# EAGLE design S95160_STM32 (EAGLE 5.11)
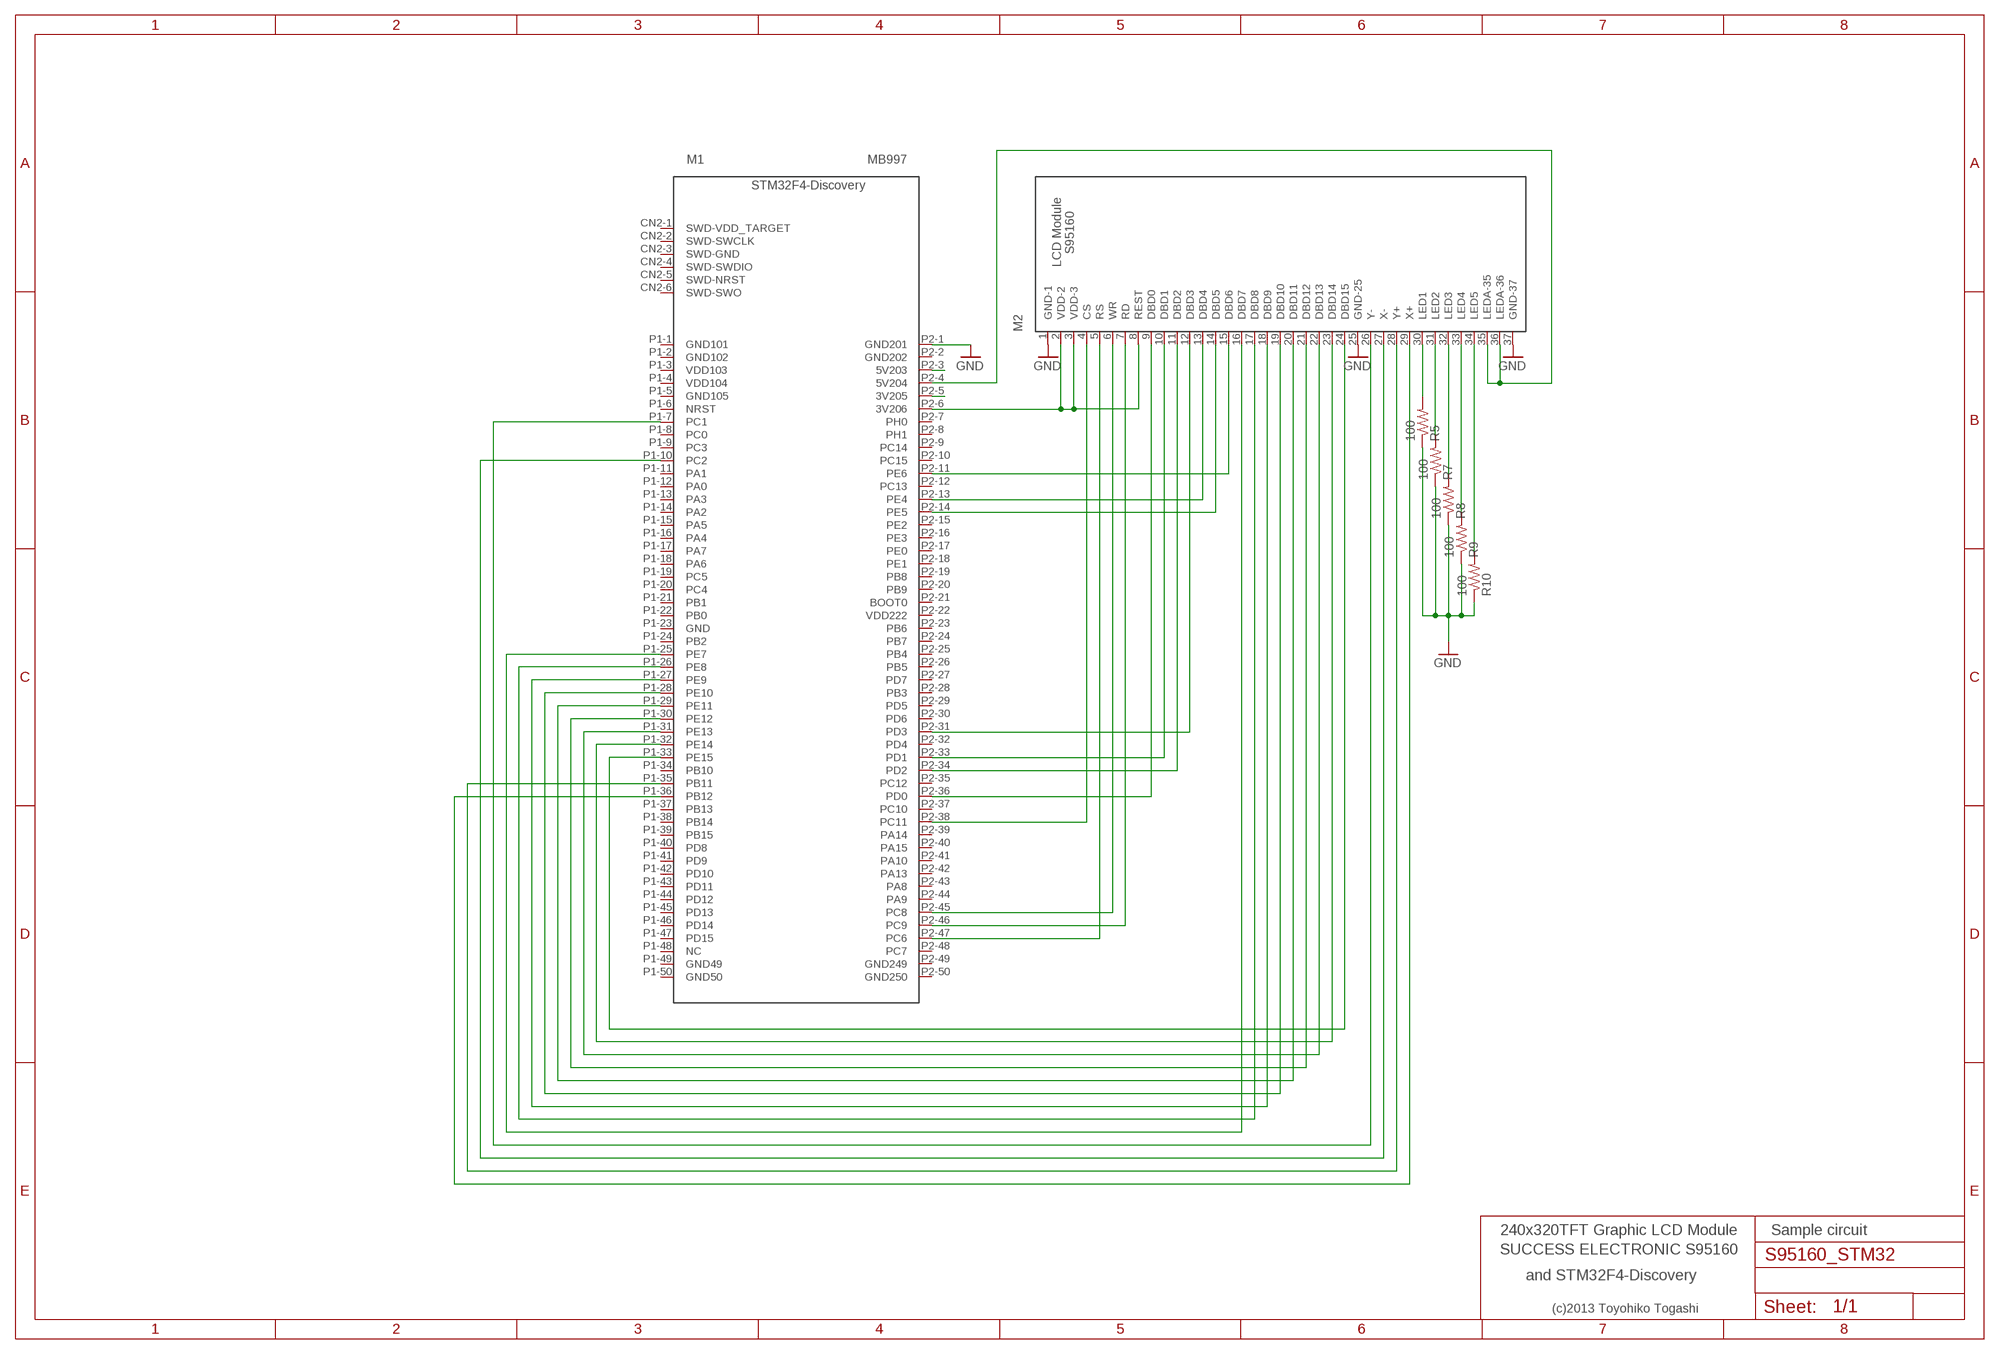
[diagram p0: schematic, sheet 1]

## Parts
M1  MB997  [MB997]
M2  S95160  [S95160]
R5  100  R-US_0204/5  [0204/5]
R7  100  R-US_0204/5  [0204/5]
R8  100  R-US_0204/5  [0204/5]
R9  100  R-US_0204/5  [0204/5]
R10  100  R-US_0204/5  [0204/5]

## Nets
GND: M1.P2-1(GND201) M2.1(GND-1) M2.25(GND-25) M2.37(GND-37) R5.1 R7.1 R8.1 R9.1 R10.1
N$1: M1.P2-36(PD0) M2.9(DBD0)
N$2: M1.P2-33(PD1) M2.10(DBD1)
N$3: M1.P2-6(3V206) M2.2(VDD-2) M2.3(VDD-3) M2.8(REST)
N$5: M1.P2-3(5V203)
N$6: M1.P2-5(3V205)
N$11: M1.P2-34(PD2) M2.11(DBD2)
N$14: M1.P2-4(5V204) M2.35(LEDA-35) M2.36(LEDA-36)
N$15: M1.P2-31(PD3) M2.12(DBD3)
N$17: M1.P2-13(PE4) M2.13(DBD4)
N$18: M1.P2-14(PE5) M2.14(DBD5)
N$19: M1.P2-11(PE6) M2.15(DBD6)
N$21: M1.P1-25(PE7) M2.16(DBD7)
N$22: M1.P1-26(PE8) M2.17(DBD8)
N$23: M1.P1-27(PE9) M2.18(DBD9)
N$24: M1.P1-28(PE10) M2.19(DBD10)
N$27: M1.P1-29(PE11) M2.20(DBD11)
N$28: M1.P1-30(PE12) M2.21(DBD12)
N$29: M1.P1-31(PE13) M2.22(DBD13)
N$30: M1.P1-32(PE14) M2.23(DBD14)
N$31: M1.P2-47(PC6) M2.5(RS)
N$32: M1.P1-33(PE15) M2.24(DBD15)
N$33: M1.P2-45(PC8) M2.6(WR)
N$34: M1.P2-46(PC9) M2.7(RD)
N$35: M1.P2-38(PC11) M2.4(CS)
N$36: M1.P1-7(PC1) M2.26(Y-)
N$37: M1.P1-10(PC2) M2.27(X-)
N$38: M1.P1-35(PB11) M2.28(Y+)
N$39: M1.P1-36(PB12) M2.29(X+)
N$42: M2.30(LED1) R5.2
N$43: M2.31(LED2) R7.2
N$44: M2.32(LED3) R8.2
N$45: M2.33(LED4) R9.2
N$46: M2.34(LED5) R10.2
Unconnected: M1.CN2-1(SWD-VDD_TARGET) M1.CN2-2(SWD-SWCLK) M1.CN2-3(SWD-GND) M1.CN2-4(SWD-SWDIO) M1.CN2-5(SWD-NRST) M1.CN2-6(SWD-SWO) M1.P1-1(GND101) M1.P1-2(GND102) M1.P1-3(VDD103) M1.P1-4(VDD104) M1.P1-5(GND105) M1.P1-6(NRST) M1.P1-8(PC0) M1.P1-9(PC3) M1.P1-11(PA1) M1.P1-12(PA0) M1.P1-13(PA3) M1.P1-14(PA2) M1.P1-15(PA5) M1.P1-16(PA4) M1.P1-17(PA7) M1.P1-18(PA6) M1.P1-19(PC5) M1.P1-20(PC4) M1.P1-21(PB1) M1.P1-22(PB0) M1.P1-23(GND) M1.P1-24(PB2) M1.P1-34(PB10) M1.P1-37(PB13) M1.P1-38(PB14) M1.P1-39(PB15) M1.P1-40(PD8) M1.P1-41(PD9) M1.P1-42(PD10) M1.P1-43(PD11) M1.P1-44(PD12) M1.P1-45(PD13) M1.P1-46(PD14) M1.P1-47(PD15) M1.P1-48(NC) M1.P1-49(GND49) M1.P1-50(GND50) M1.P2-2(GND202) M1.P2-7(PH0) M1.P2-8(PH1) M1.P2-9(PC14) M1.P2-10(PC15) M1.P2-12(PC13) M1.P2-15(PE2) M1.P2-16(PE3) M1.P2-17(PE0) M1.P2-18(PE1) M1.P2-19(PB8) M1.P2-20(PB9) M1.P2-21(BOOT0) M1.P2-22(VDD222) M1.P2-23(PB6) M1.P2-24(PB7) M1.P2-25(PB4) M1.P2-26(PB5) M1.P2-27(PD7) M1.P2-28(PB3) M1.P2-29(PD5) M1.P2-30(PD6) M1.P2-32(PD4) M1.P2-35(PC12) M1.P2-37(PC10) M1.P2-39(PA14) M1.P2-40(PA15) M1.P2-41(PA10) M1.P2-42(PA13) M1.P2-43(PA8) M1.P2-44(PA9) M1.P2-48(PC7) M1.P2-49(GND249) M1.P2-50(GND250)

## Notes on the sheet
- 240x320TFT Graphic LCD Module | Sample circuit
- SUCCESS ELECTRONIC S95160
- and STM32F4-Discovery
- (c)2013 Toyohiko Togashi

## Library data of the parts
M1 = TOG:MB997: STMicroelectronics STM32F4-Discovery
M2 = TOG:S95160: 3.2' TFT LCD Module 240x320dot SUCCESS ELECTRONIC CO.,LTD.
R5 R7-R10 = rcl:R-US_: RESISTOR, American symbol

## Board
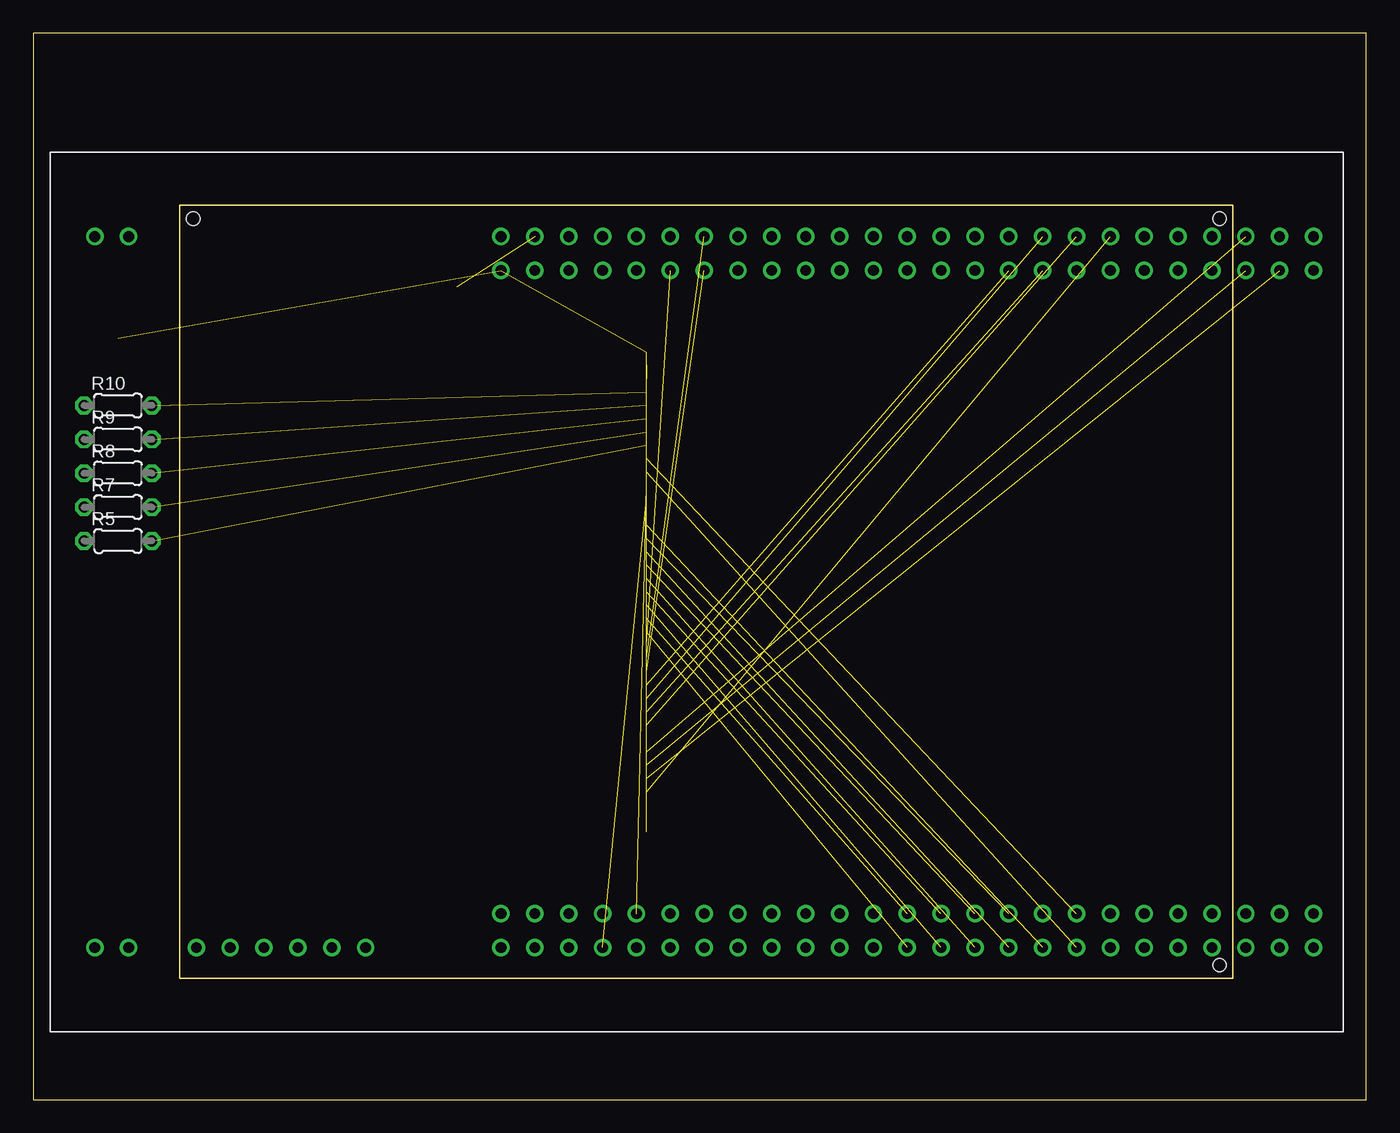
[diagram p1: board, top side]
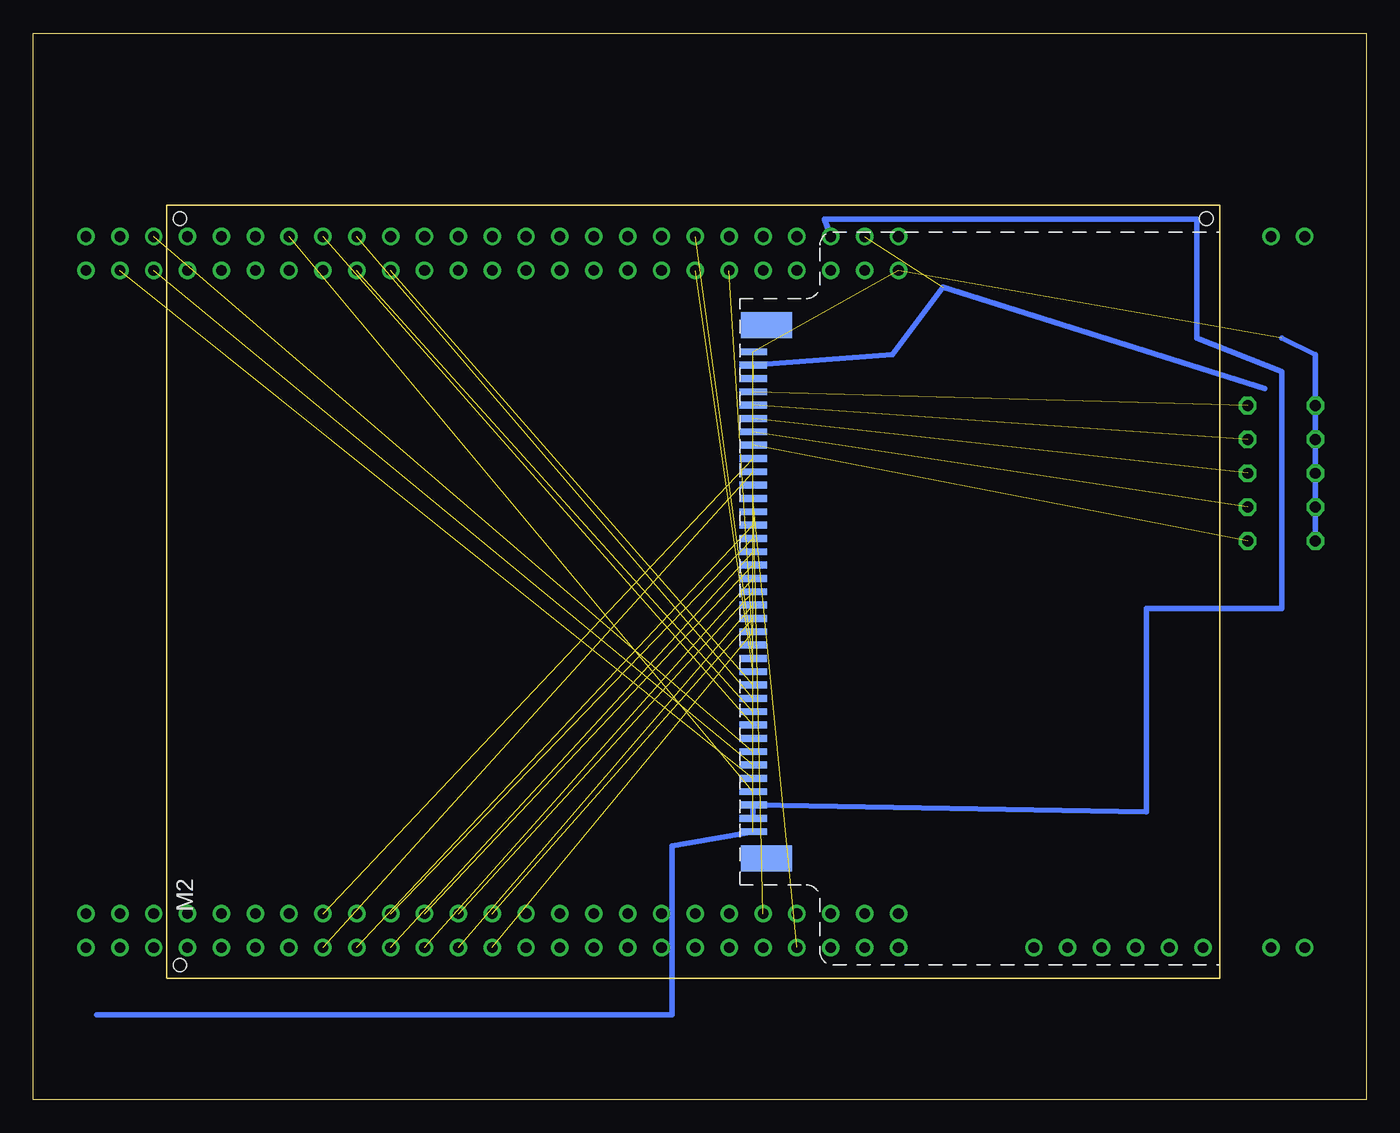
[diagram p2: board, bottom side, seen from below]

Size 100 x 80 mm. Coordinates in mm from the lower left corner, seen from the top.
Outline: 0,0 100,0 100,80 0,80 0,0
Copper layers (1*16): Top 0.035mm / dielectric 1.5mm / Bottom 0.035mm
Design rules "default": minimum track width 10mil, minimum drill 24mil, track to track 8mil, track to pad 8mil, pad to pad 8mil, via to via 8mil, smd to smd 8mil, copper to edge 40mil, drill to drill 8mil, minimum pad ring 10mil, minimum via ring 8mil, stop-mask expansion 4mil, vias tented up to drill 0mil, thermal gap 10mil

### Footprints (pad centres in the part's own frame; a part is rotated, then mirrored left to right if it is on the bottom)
MB997 = drill 0.8 round: CN2-1 6.33,-10.96; CN2-2 6.33,-13.5; CN2-3 6.33,-16.04; CN2-4 6.33,-18.58; CN2-5 6.33,-21.12; CN2-6 6.33,-23.66; P1-1 6.33,-33.82; P1-2 8.87,-33.82; P1-3 6.33,-36.36; P1-4 8.87,-36.36; P1-5 6.33,-38.9; P1-6 8.87,-38.9; P1-7 6.33,-41.44; P1-8 8.87,-41.44; P1-9 6.33,-43.98; P1-10 8.87,-43.98; P1-11 6.33,-46.52; P1-12 8.87,-46.52; P1-13 6.33,-49.06; P1-14 8.87,-49.06; P1-15 6.33,-51.6; P1-16 8.87,-51.6; P1-17 6.33,-54.14; P1-18 8.87,-54.14; P1-19 6.33,-56.68; P1-20 8.87,-56.68; P1-21 6.33,-59.22; P1-22 8.87,-59.22; P1-23 6.33,-61.76; P1-24 8.87,-61.76; P1-25 6.33,-64.3; P1-26 8.87,-64.3; P1-27 6.33,-66.84; P1-28 8.87,-66.84; P1-29 6.33,-69.38; P1-30 8.87,-69.38; P1-31 6.33,-71.92; P1-32 8.87,-71.92; P1-33 6.33,-74.46; P1-34 8.87,-74.46; P1-35 6.33,-77; P1-36 8.87,-77; P1-37 6.33,-79.54; P1-38 8.87,-79.54; P1-39 6.33,-82.08; P1-40 8.87,-82.08; P1-41 6.33,-84.62; P1-42 8.87,-84.62; P1-43 6.33,-87.16; P1-44 8.87,-87.16; P1-45 6.33,-89.7; P1-46 8.87,-89.7; P1-47 6.33,-92.24; P1-48 8.87,-92.24; P1-49 6.33,-94.78; P1-50 8.87,-94.78; P2-1 57.13,-33.82; P2-2 59.67,-33.82; P2-3 57.13,-36.36; P2-4 59.67,-36.36; P2-5 57.13,-38.9; P2-6 59.67,-38.9; P2-7 57.13,-41.44; P2-8 59.67,-41.44; P2-9 57.13,-43.98; P2-10 59.67,-43.98; P2-11 57.13,-46.52; P2-12 59.67,-46.52; P2-13 57.13,-49.06; P2-14 59.67,-49.06; P2-15 57.13,-51.6; P2-16 59.67,-51.6; P2-17 57.13,-54.14; P2-18 59.67,-54.14; P2-19 57.13,-56.68; P2-20 59.67,-56.68; P2-21 57.13,-59.22; P2-22 59.67,-59.22; P2-23 57.13,-61.76; P2-24 59.67,-61.76; P2-25 57.13,-64.3; P2-26 59.67,-64.3; P2-27 57.13,-66.84; P2-28 59.67,-66.84; P2-29 57.13,-69.38; P2-30 59.67,-69.38; P2-31 57.13,-71.92; P2-32 59.67,-71.92; P2-33 57.13,-74.46; P2-34 59.67,-74.46; P2-35 57.13,-77; P2-36 59.67,-77; P2-37 57.13,-79.54; P2-38 59.67,-79.54; P2-39 57.13,-82.08; P2-40 59.67,-82.08; P2-41 57.13,-84.62; P2-42 59.67,-84.62; P2-43 57.13,-87.16; P2-44 59.67,-87.16; P2-45 57.13,-89.7; P2-46 59.67,-89.7; P2-47 57.13,-92.24; P2-48 59.67,-92.24; P2-49 57.13,-94.78; P2-50 59.67,-94.78; P$107 6.33,-3.34; P$108 6.33,-5.88; P$109 59.67,-3.34; P$110 59.67,-5.88
S95160 = smd 0.508 x 2.032: 1 -18,-1; 2 -17,-1; 3 -16,-1; 4 -15,-1; 5 -14,-1; 6 -13,-1; 7 -12,-1; 8 -11,-1; 9 -10,-1; 10 -9,-1; 11 -8,-1; 12 -7,-1; 13 -6,-1; 14 -5,-1; 15 -4,-1; 16 -3,-1; 17 -2,-1; 18 -1,-1; 19 0,-1; 20 1,-1; 21 2,-1; 22 3,-1; 23 4,-1; 24 5,-1; 25 6,-1; 26 7,-1; 27 8,-1; 28 9,-1; 29 10,-1; 30 11,-1; 31 12,-1; 32 13,-1; 33 14,-1; 34 15,-1; 35 16,-1; 36 17,-1; 37 18,-1 | smd 1.93 x 3.81: P$38 -20,-2; P$39 20,-2 | hole 1: -28,42; 28,42; 28,-35
0204/5 = drill 0.813 octagon: 1 -2.54,0; 2 2.54,0

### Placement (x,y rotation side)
M1  1.27,5.08 90 top
M2  46.99,38.1 90 bottom
R5  6.35,41.91 0 top
R7  6.35,44.45 0 top
R8  6.35,46.99 0 top
R9  6.35,49.53 0 top
R10  6.35,52.07 0 top

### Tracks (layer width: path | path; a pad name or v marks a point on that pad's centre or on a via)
GND  (4 unrouted)
  Bottom 0.406: 95.25,6.35 62.23,6.35 52.07,6.35 52.07,19.05 M2.1 | R5.1 R7.1 R8.1 R9.1 R10.1 3.81,55.88 6.35,57.15
N$1  (1 unrouted)
N$2  (1 unrouted)
N$3  (1 unrouted)
  Bottom 0.406: M2.2 M2.3 16.51,21.59 16.51,36.83 6.35,36.83 6.35,54.61 12.7,57.15 12.7,66.04 40.64,66.04 M1.P2-6
N$11  (1 unrouted)
N$14  (2 unrouted)
  Bottom 0.406: 7.62,53.34 31.75,60.96 35.56,55.88 M2.36
N$15  (1 unrouted)
N$17  (1 unrouted)
N$18  (1 unrouted)
N$19  (1 unrouted)
N$21  (1 unrouted)
N$22  (1 unrouted)
N$23  (1 unrouted)
N$24  (1 unrouted)
N$27  (1 unrouted)
N$28  (1 unrouted)
N$29  (1 unrouted)
N$30  (1 unrouted)
N$31  (1 unrouted)
N$32  (1 unrouted)
N$33  (1 unrouted)
N$34  (1 unrouted)
N$35  (1 unrouted)
N$36  (1 unrouted)
N$37  (1 unrouted)
N$38  (1 unrouted)
N$39  (1 unrouted)
N$42  (1 unrouted)
N$43  (1 unrouted)
N$44  (1 unrouted)
N$45  (1 unrouted)
N$46  (1 unrouted)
